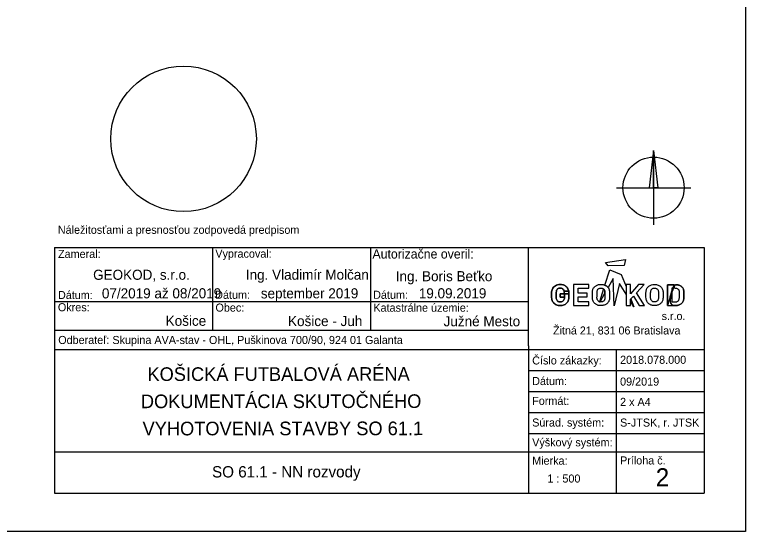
# Model space of a CAD drawing. Extents: x -263993 to -263783, y -1242294 to -1242146.
# Drawn here: x -263888 to -263783.1, y -1242294.3 to -1242220 of the extents above; entities that cross this region are included whole.
import ezdxf

# ---------------------------------------------------------------- set-up
doc = ezdxf.new("R2010")
doc.units = 0
doc.layers.add('RAM_NA_TLAC_A3_1-500', color=7, linetype='Continuous')
doc.layers.add('ROZPISKA', color=7, linetype='Continuous')

msp = doc.modelspace()

# ---------------------------------------------------------------- linework, layer by layer
at = {"layer": 'RAM_NA_TLAC_A3_1-500'}
msp.add_lwpolyline([(-263993.08, -1242145.75), (-263783.08, -1242145.75), (-263783.08, -1242294.25), (-263993.08, -1242294.25)], close=True, dxfattribs=at)
at = {"layer": 'ROZPISKA'}
for p, q in [((-263796.27, -1242239.54), (-263796.9, -1242244.87)), ((-263796.27, -1242239.54), (-263796.27, -1242250.2)), ((-263796.27, -1242239.54), (-263795.64, -1242244.87)), ((-263801.6, -1242244.87), (-263790.94, -1242244.87)), ((-263882.29, -1242253.48), (-263789.02, -1242253.48)), ((-263882.29, -1242253.48), (-263882.29, -1242288.77)), ((-263859.6, -1242253.48), (-263859.6, -1242265.33)), ((-263836.92, -1242253.49), (-263836.91, -1242265.33)), ((-263814.22, -1242267.6), (-263814.23, -1242253.48)), ((-263789.02, -1242253.48), (-263789.02, -1242288.77)), ((-263803.26, -1242258.87), (-263802.53, -1242256.66)), ((-263802.53, -1242256.66), (-263800.91, -1242257.35)), ((-263800.91, -1242257.35), (-263800.22, -1242259.09)), ((-263803.86, -1242258.77), (-263803.81, -1242258.76)), ((-263802.07, -1242257.92), (-263802.8, -1242259.22)), ((-263801.93, -1242261.87), (-263802.07, -1242257.92)), ((-263801.15, -1242258.66), (-263801.93, -1242261.87)), ((-263800.22, -1242260.15), (-263801.15, -1242258.66)), ((-263808.43, -1242259.73), (-263809.09, -1242259.73)), ((-263809.09, -1242259.73), (-263808.43, -1242259.73)), ((-263803.45, -1242259.42), (-263804.05, -1242261.26)), ((-263803.85, -1242259.3), (-263803.81, -1242259.3)), ((-263803.85, -1242259.3), (-263803.81, -1242259.3)), ((-263799.59, -1242258.8), (-263800.22, -1242258.8)), ((-263800.22, -1242259.09), (-263800.22, -1242260.15)), ((-263798.43, -1242258.8), (-263799.59, -1242260.11)), ((-263799.59, -1242260.11), (-263799.59, -1242258.8)), ((-263798.74, -1242260), (-263797.64, -1242258.8)), ((-263797.64, -1242258.8), (-263798.43, -1242258.8)), ((-263794.29, -1242258.81), (-263793.33, -1242258.81)), ((-263794.29, -1242261.79), (-263794.29, -1242258.81)), ((-263794.29, -1242258.81), (-263794.29, -1242261.79)), ((-263793.33, -1242258.81), (-263794.29, -1242258.81)), ((-263793.63, -1242259.33), (-263793.63, -1242261.27)), ((-263793.63, -1242259.33), (-263793.63, -1242261.27)), ((-263799.53, -1242260.84), (-263799.09, -1242261.98)), ((-263797.58, -1242261.79), (-263798.74, -1242260)), ((-263882.29, -1242261.23), (-263814.23, -1242261.23)), ((-263799.09, -1242261.98), (-263799.58, -1242261.18)), ((-263798.33, -1242261.79), (-263797.58, -1242261.79)), ((-263882.29, -1242265.33), (-263814.23, -1242265.33)), ((-263882.29, -1242268.11), (-263814.22, -1242268.1)), ((-263814.22, -1242267.6), (-263814.23, -1242276.68)), ((-263814.22, -1242268.1), (-263789.02, -1242268.1)), ((-263801.62, -1242268.1), (-263801.62, -1242277.18)), ((-263814.22, -1242271.13), (-263789.02, -1242271.13)), ((-263814.23, -1242274.15), (-263789.02, -1242274.15)), ((-263814.23, -1242276.68), (-263814.23, -1242288.77)), ((-263814.23, -1242277.18), (-263789.01, -1242277.18)), ((-263801.62, -1242277.18), (-263801.62, -1242288.77)), ((-263814.23, -1242280.2), (-263789.01, -1242280.2)), ((-263882.29, -1242282.82), (-263789.02, -1242282.82)), ((-263882.29, -1242288.77), (-263789.02, -1242288.77))]:
    msp.add_line(p, q, dxfattribs=at)
for points in [[(-263796.27, -1242239.54), (-263795.64, -1242244.87), (-263796.27, -1242244.87)], [(-263803.18, -1242255.63), (-263800.29, -1242255.21), (-263800.49, -1242256.04), (-263802.8, -1242256.11)], [(-263807.77, -1242258.79), (-263807.77, -1242261.79), (-263805.57, -1242261.79), (-263805.57, -1242261.26), (-263807.11, -1242261.26), (-263807.11, -1242260.54), (-263805.8, -1242260.54), (-263805.8, -1242260.02), (-263807.11, -1242260.02), (-263807.11, -1242259.32), (-263805.57, -1242259.32), (-263805.57, -1242258.79)]]:
    msp.add_lwpolyline(points, close=True, dxfattribs=at)
for points in [[(-263803.25, -1242260.03), (-263803.25, -1242259.96), (-263803.25, -1242259.88), (-263803.26, -1242259.81), (-263803.27, -1242259.73), (-263803.29, -1242259.67), (-263803.31, -1242259.59), (-263803.35, -1242259.52), (-263803.4, -1242259.47), (-263803.45, -1242259.42)], [(-263802.8, -1242259.22), (-263802.82, -1242259.19), (-263802.85, -1242259.15), (-263802.89, -1242259.11), (-263802.94, -1242259.07), (-263802.98, -1242259.04), (-263803.03, -1242259), (-263803.07, -1242258.98), (-263803.12, -1242258.95), (-263803.17, -1242258.92), (-263803.22, -1242258.89), (-263803.26, -1242258.87)], [(-263800.22, -1242258.8), (-263800.22, -1242261.79), (-263799.58, -1242261.79), (-263799.58, -1242260.9), (-263799.16, -1242260.45), (-263798.33, -1242261.79)], [(-263809.07, -1242260.61), (-263809.69, -1242260.61), (-263809.69, -1242260.12), (-263808.42, -1242260.12)], [(-263808.42, -1242260.12), (-263809.69, -1242260.12), (-263809.69, -1242260.61), (-263809.07, -1242260.61)], [(-263803.95, -1242261.29), (-263803.25, -1242260.03)], [(-263799.58, -1242261.18), (-263799.58, -1242260.9), (-263799.53, -1242260.84)], [(-263804.05, -1242261.26), (-263804.04, -1242261.26), (-263804.02, -1242261.27), (-263804, -1242261.28), (-263803.98, -1242261.28), (-263803.96, -1242261.28), (-263803.95, -1242261.29)]]:
    msp.add_lwpolyline(points, dxfattribs=at)
for centre, radius in [((-263863.76, -1242237.86), 10.45), ((-263796.27, -1242244.87), 4.39)]:
    msp.add_circle(centre, radius, dxfattribs=at)
for points in [[(-263803.81, -1242258.76), (-263803.79, -1242258.76), (-263803.7, -1242258.76), (-263803.53, -1242258.8), (-263803.31, -1242258.84), (-263803.09, -1242258.96), (-263802.9, -1242259.09), (-263802.74, -1242259.28), (-263802.65, -1242259.49), (-263802.59, -1242259.72), (-263802.6, -1242260.08), (-263802.59, -1242260.45), (-263802.59, -1242260.82), (-263802.63, -1242261.05), (-263802.71, -1242261.24), (-263802.82, -1242261.41), (-263802.97, -1242261.54), (-263803.14, -1242261.66), (-263803.34, -1242261.74), (-263803.56, -1242261.81), (-263803.79, -1242261.82), (-263804.02, -1242261.81), (-263804.22, -1242261.79), (-263804.39, -1242261.71), (-263804.55, -1242261.62), (-263804.7, -1242261.52), (-263804.84, -1242261.37), (-263804.96, -1242261.18), (-263805.03, -1242260.94), (-263805.07, -1242260.55), (-263805.03, -1242260.18), (-263805.05, -1242259.83), (-263805.02, -1242259.64), (-263804.98, -1242259.44), (-263804.88, -1242259.27), (-263804.76, -1242259.12), (-263804.62, -1242259), (-263804.45, -1242258.91), (-263804.26, -1242258.82), (-263804.05, -1242258.78), (-263803.92, -1242258.77), (-263803.86, -1242258.77)], [(-263796.12, -1242258.76), (-263796.34, -1242258.78), (-263796.57, -1242258.83), (-263796.77, -1242258.91), (-263796.93, -1242259), (-263797.06, -1242259.13), (-263797.18, -1242259.27), (-263797.28, -1242259.44), (-263797.33, -1242259.64), (-263797.36, -1242259.83), (-263797.36, -1242260.04), (-263797.36, -1242260.68), (-263797.34, -1242260.92), (-263797.25, -1242261.19), (-263797.14, -1242261.38), (-263797.02, -1242261.5), (-263796.85, -1242261.62), (-263796.7, -1242261.71), (-263796.53, -1242261.78), (-263796.33, -1242261.81), (-263796.12, -1242261.82), (-263795.86, -1242261.8), (-263795.64, -1242261.73), (-263795.46, -1242261.66), (-263795.28, -1242261.53), (-263795.14, -1242261.41), (-263795.03, -1242261.25), (-263794.95, -1242261.04), (-263794.91, -1242260.83), (-263794.9, -1242260.57), (-263794.9, -1242259.95), (-263794.91, -1242259.71), (-263794.97, -1242259.5), (-263795.07, -1242259.28), (-263795.21, -1242259.11), (-263795.42, -1242258.95), (-263795.62, -1242258.86), (-263795.85, -1242258.8), (-263796.07, -1242258.76), (-263796.12, -1242258.76), (-263796.12, -1242258.76), (-263796.12, -1242258.76)], [(-263808.42, -1242260.12), (-263808.42, -1242260.5), (-263808.43, -1242260.84), (-263808.5, -1242261.14), (-263808.64, -1242261.38), (-263808.87, -1242261.58), (-263809.1, -1242261.72), (-263809.41, -1242261.8), (-263809.69, -1242261.82), (-263809.98, -1242261.8), (-263810.27, -1242261.7), (-263810.53, -1242261.54), (-263810.72, -1242261.34), (-263810.85, -1242261.08), (-263810.91, -1242260.79), (-263810.92, -1242260.59), (-263810.92, -1242260), (-263810.9, -1242259.68), (-263810.81, -1242259.41), (-263810.66, -1242259.17), (-263810.37, -1242258.94), (-263810.06, -1242258.81), (-263809.7, -1242258.77), (-263809.32, -1242258.8), (-263808.92, -1242258.96), (-263808.61, -1242259.25), (-263808.43, -1242259.73), (-263808.42, -1242260.12), (-263808.43, -1242259.73)], [(-263808.43, -1242259.73), (-263808.61, -1242259.25), (-263808.92, -1242258.96), (-263809.32, -1242258.8), (-263809.7, -1242258.77), (-263810.06, -1242258.81), (-263810.37, -1242258.94), (-263810.66, -1242259.17), (-263810.81, -1242259.41), (-263810.9, -1242259.68), (-263810.92, -1242260), (-263810.92, -1242260.59), (-263810.91, -1242260.79), (-263810.85, -1242261.08), (-263810.72, -1242261.34), (-263810.53, -1242261.54), (-263810.27, -1242261.7), (-263809.98, -1242261.8), (-263809.69, -1242261.82), (-263809.41, -1242261.8), (-263809.1, -1242261.72), (-263808.87, -1242261.58), (-263808.64, -1242261.38), (-263808.5, -1242261.14), (-263808.43, -1242260.84), (-263808.42, -1242260.5), (-263808.42, -1242260.12), (-263808.43, -1242259.73), (-263808.42, -1242260.12)], [(-263809.09, -1242259.73), (-263809.15, -1242259.56), (-263809.3, -1242259.4), (-263809.49, -1242259.31), (-263809.69, -1242259.3), (-263809.89, -1242259.32), (-263810.05, -1242259.41), (-263810.17, -1242259.54), (-263810.23, -1242259.68), (-263810.23, -1242259.88), (-263810.25, -1242260.1), (-263810.25, -1242260.37), (-263810.25, -1242260.69), (-263810.22, -1242260.92), (-263810.14, -1242261.1), (-263810.01, -1242261.21), (-263809.86, -1242261.27), (-263809.7, -1242261.29), (-263809.51, -1242261.28), (-263809.31, -1242261.2), (-263809.17, -1242261.07), (-263809.09, -1242260.91), (-263809.07, -1242260.73), (-263809.07, -1242260.61), (-263809.09, -1242259.73), (-263809.07, -1242260.61)], [(-263809.07, -1242260.61), (-263809.07, -1242260.73), (-263809.09, -1242260.91), (-263809.17, -1242261.07), (-263809.31, -1242261.2), (-263809.51, -1242261.28), (-263809.7, -1242261.29), (-263809.86, -1242261.27), (-263810.01, -1242261.21), (-263810.14, -1242261.1), (-263810.22, -1242260.92), (-263810.25, -1242260.69), (-263810.25, -1242260.37), (-263810.25, -1242260.1), (-263810.23, -1242259.88), (-263810.23, -1242259.68), (-263810.17, -1242259.54), (-263810.05, -1242259.41), (-263809.89, -1242259.32), (-263809.69, -1242259.3), (-263809.49, -1242259.31), (-263809.3, -1242259.4), (-263809.15, -1242259.56), (-263809.09, -1242259.73), (-263809.07, -1242260.61), (-263809.09, -1242259.73)], [(-263803.81, -1242259.3), (-263803.79, -1242259.3), (-263803.72, -1242259.3), (-263803.6, -1242259.33), (-263803.47, -1242259.39), (-263803.35, -1242259.51), (-263803.27, -1242259.68), (-263803.24, -1242259.86), (-263803.25, -1242260.06), (-263803.24, -1242260.28), (-263803.25, -1242260.49), (-263803.24, -1242260.7), (-263803.27, -1242260.87), (-263803.31, -1242261.02), (-263803.4, -1242261.16), (-263803.55, -1242261.25), (-263803.7, -1242261.29), (-263803.83, -1242261.29), (-263803.94, -1242261.29), (-263804.06, -1242261.26), (-263804.18, -1242261.19), (-263804.29, -1242261.08), (-263804.37, -1242260.92), (-263804.4, -1242260.72), (-263804.39, -1242260.49), (-263804.39, -1242260.22), (-263804.38, -1242259.97), (-263804.38, -1242259.77), (-263804.35, -1242259.6), (-263804.26, -1242259.47), (-263804.13, -1242259.37), (-263803.99, -1242259.31), (-263803.89, -1242259.3), (-263803.85, -1242259.3)], [(-263803.81, -1242259.3), (-263803.79, -1242259.3), (-263803.72, -1242259.3), (-263803.6, -1242259.33), (-263803.47, -1242259.39), (-263803.35, -1242259.51), (-263803.27, -1242259.68), (-263803.24, -1242259.86), (-263803.25, -1242260.06), (-263803.24, -1242260.28), (-263803.25, -1242260.49), (-263803.24, -1242260.7), (-263803.27, -1242260.87), (-263803.31, -1242261.02), (-263803.4, -1242261.16), (-263803.55, -1242261.25), (-263803.7, -1242261.29), (-263803.83, -1242261.29), (-263803.94, -1242261.29), (-263804.06, -1242261.26), (-263804.18, -1242261.19), (-263804.29, -1242261.08), (-263804.37, -1242260.92), (-263804.4, -1242260.72), (-263804.39, -1242260.49), (-263804.39, -1242260.22), (-263804.38, -1242259.97), (-263804.38, -1242259.77), (-263804.35, -1242259.6), (-263804.26, -1242259.47), (-263804.13, -1242259.37), (-263803.99, -1242259.31), (-263803.89, -1242259.3), (-263803.85, -1242259.3)], [(-263796.12, -1242259.3), (-263796.28, -1242259.31), (-263796.44, -1242259.38), (-263796.57, -1242259.48), (-263796.64, -1242259.6), (-263796.68, -1242259.76), (-263796.69, -1242259.94), (-263796.7, -1242260.21), (-263796.7, -1242260.52), (-263796.7, -1242260.73), (-263796.67, -1242260.92), (-263796.59, -1242261.08), (-263796.48, -1242261.19), (-263796.37, -1242261.26), (-263796.24, -1242261.29), (-263796.14, -1242261.29), (-263796.03, -1242261.29), (-263795.87, -1242261.25), (-263795.71, -1242261.14), (-263795.63, -1242261.02), (-263795.58, -1242260.87), (-263795.56, -1242260.7), (-263795.56, -1242260.51), (-263795.56, -1242260.27), (-263795.56, -1242260.05), (-263795.56, -1242259.87), (-263795.6, -1242259.66), (-263795.66, -1242259.52), (-263795.78, -1242259.4), (-263795.92, -1242259.33), (-263796.04, -1242259.3), (-263796.12, -1242259.3), (-263796.12, -1242259.3), (-263796.12, -1242259.3)], [(-263793.33, -1242258.81), (-263793.02, -1242258.81), (-263792.83, -1242258.82), (-263792.68, -1242258.85), (-263792.5, -1242258.91), (-263792.32, -1242259.01), (-263792.15, -1242259.18), (-263792.02, -1242259.37), (-263791.95, -1242259.54), (-263791.91, -1242259.82), (-263791.91, -1242259.95), (-263791.91, -1242260.55), (-263791.91, -1242260.74), (-263791.93, -1242260.9), (-263791.96, -1242261.07), (-263792.04, -1242261.28), (-263792.19, -1242261.47), (-263792.41, -1242261.64), (-263792.59, -1242261.72), (-263792.77, -1242261.77), (-263792.92, -1242261.79), (-263792.98, -1242261.79), (-263794.29, -1242261.79), (-263793.33, -1242258.81), (-263794.29, -1242261.79)], [(-263794.29, -1242261.79), (-263792.98, -1242261.79), (-263792.92, -1242261.79), (-263792.77, -1242261.77), (-263792.59, -1242261.72), (-263792.41, -1242261.64), (-263792.19, -1242261.47), (-263792.04, -1242261.28), (-263791.96, -1242261.07), (-263791.93, -1242260.9), (-263791.91, -1242260.74), (-263791.91, -1242260.55), (-263791.91, -1242259.95), (-263791.91, -1242259.82), (-263791.95, -1242259.54), (-263792.02, -1242259.37), (-263792.15, -1242259.18), (-263792.32, -1242259.01), (-263792.5, -1242258.91), (-263792.68, -1242258.85), (-263792.83, -1242258.82), (-263793.02, -1242258.81), (-263793.33, -1242258.81), (-263794.29, -1242261.79), (-263793.33, -1242258.81)], [(-263793.63, -1242261.27), (-263793.44, -1242261.27), (-263793.24, -1242261.28), (-263793.04, -1242261.27), (-263793, -1242261.28), (-263792.92, -1242261.26), (-263792.8, -1242261.2), (-263792.65, -1242261.09), (-263792.58, -1242260.91), (-263792.56, -1242260.71), (-263792.56, -1242260.43), (-263792.56, -1242260.11), (-263792.56, -1242259.85), (-263792.57, -1242259.67), (-263792.64, -1242259.55), (-263792.77, -1242259.42), (-263792.92, -1242259.36), (-263793.13, -1242259.33), (-263793.27, -1242259.33), (-263793.55, -1242259.33), (-263793.63, -1242259.33)], [(-263793.63, -1242261.27), (-263793.44, -1242261.27), (-263793.24, -1242261.28), (-263793.04, -1242261.27), (-263793, -1242261.28), (-263792.92, -1242261.26), (-263792.8, -1242261.2), (-263792.65, -1242261.09), (-263792.58, -1242260.91), (-263792.56, -1242260.71), (-263792.56, -1242260.43), (-263792.56, -1242260.11), (-263792.56, -1242259.85), (-263792.57, -1242259.67), (-263792.64, -1242259.55), (-263792.77, -1242259.42), (-263792.92, -1242259.36), (-263793.13, -1242259.33), (-263793.27, -1242259.33), (-263793.55, -1242259.33), (-263793.63, -1242259.33)]]:
    msp.add_open_spline(points, degree=3, dxfattribs=at)

# ---------------------------------------------------------------- texts
for s, height, rotation, p in [('Náležitosťami a presnosťou zodpovedá predpisom', 1.1593, 0.0016, (-263881.82, -1242251.5)), ('Zameral:', 1.159, 0.0016, (-263881.79, -1242254.97)), ('Vypracoval:', 1.1593, 0.0016, (-263859.2, -1242254.93)), ('Autorizačne overil:', 1.3214, 0.0016, (-263836.64, -1242255.05)), ('GEOKOD, s.r.o.', 1.4488, 0.0456, (-263876.75, -1242258.11)), ('Ing. Vladimír Molčan', 1.4491, 0.0456, (-263854.82, -1242258.1)), ('Ing. Boris Beťko', 1.4498, 0.0456, (-263833.29, -1242258.32)), ('Dátum:', 1.159, 0.0016, (-263881.8, -1242260.87)), ('07/2019 až 08/2019', 1.4488, 0.0456, (-263875.49, -1242260.78)), ('Dátum:', 1.159, 0.0016, (-263859.22, -1242260.84)), ('september 2019', 1.4488, 0.0456, (-263852.67, -1242260.78)), ('Dátum:', 1.159, 0.0016, (-263836.54, -1242260.84)), ('19.09.2019', 1.449, 0.0456, (-263829.98, -1242260.77)), ('Okres:', 1.159, 0.0016, (-263881.81, -1242262.63)), ('Obec:', 1.159, 0.0016, (-263859.18, -1242262.68)), ('Katastrálne územie:', 1.1593, 0.0016, (-263836.5, -1242262.69)), ('Košice', 1.449, 0.0456, (-263866.33, -1242264.72)), ('Košice - Juh', 1.4498, 0.0456, (-263848.76, -1242264.76)), ('Južné Mesto', 1.4498, 0.0456, (-263826.42, -1242264.79)), ('s.r.o.', 1.15, 0.0016, (-263795.11, -1242263.89)), ('Žitná 21, 831 06 Bratislava', 1.1495, 0.0016, (-263810.7, -1242265.96)), ('Odberateľ: Skupina AVA-stav - OHL, Puškinova 700/90, 924 01 Galanta', 1.159, 0.0016, (-263881.76, -1242267.33)), ('Číslo zákazky:', 1.159, 0.0016, (-263813.7, -1242270.27)), ('KOŠICKÁ FUTBALOVÁ ARÉNA', 1.9572, 0.0456, (-263868.95, -1242272.64)), ('Dátum:', 1.159, 0.0016, (-263813.7, -1242273.23)), ('DOKUMENTÁCIA SKUTOČNÉHO', 1.9572, 0.0456, (-263869.89, -1242276.55)), ('Formát:', 1.159, 0.0016, (-263813.7, -1242276.08)), ('VYHOTOVENIA STAVBY SO 61.1', 1.9572, 0.0456, (-263869.65, -1242280.46)), ('Súrad. systém:', 1.159, 0.0016, (-263813.7, -1242279.19)), ('Výškový systém:', 1.159, 0.0016, (-263813.7, -1242282.04)), ('Mierka:', 1.159, 0.0016, (-263813.7, -1242284.67)), ('Príloha č.', 1.159, 0.0016, (-263801.08, -1242284.64)), ('SO 61.1 - NN rozvody', 1.6306, 0.0456, (-263859.67, -1242286.51))]:
    msp.add_text(s, height=height, rotation=rotation, dxfattribs=at).set_placement(p)
for s, height, p in [('2018.078.000', 1.161, (-263801.08, -1242270.18)), ('09/2019', 1.161, (-263801.08, -1242273.31)), ('2 x A4', 1.161, (-263801.08, -1242276.23)), ('S-JTSK, r. JTSK', 1.161, (-263801.08, -1242279.2)), ('2', 2.61, (-263795.96, -1242287.79)), ('1 : 500', 1.161, (-263811.52, -1242287.24))]:
    msp.add_text(s, height=height, dxfattribs=at).set_placement(p)

doc.saveas('drawing.dxf')
